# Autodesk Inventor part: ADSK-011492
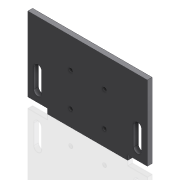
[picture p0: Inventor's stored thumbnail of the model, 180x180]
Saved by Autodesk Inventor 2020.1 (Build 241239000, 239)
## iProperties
Created: 2000-02
Part Number: ADSK-011492
Material: RA HRS
Description: PLT-24,FH,CP,02,060,040,NNCCCC,PLATE,MNT
Document SubType Name: Modeling
Designer: sspink
Density: 7.83 g/cm^3
Appearance: Métal - Acier
Mass: 672.294 g
Surface Area: 330.042 cm^2
Volume: 85.8613 cm^3
Control State: 0
Checked Out: False
Master: False
Shininess: 0.0
Length Units: 11269
Angle Units: 11279
Time Units: 11290
Mass Units: 11283
Length Display Precision: 3
Angle Display Precision: 2
Compacted: True
Cutlength: 6
Material Desc: FLAT,HRS,0.25 X 4.00
Material_number: A084338
Dimensions: 152x101x6 mm
Mass: 0,672 kg
DocNumber: ADSK-011492.ipt
Folder: 01 - Themengebiete\Simplification\01 - Packaging machine\
VDS_Category: 3D Komponenten
Density: 0.0
Volumn: 0.0
Area: 0.0
PropertySet Name: Model Information
Author: sspink
Revision Number: -
Title: PLT-24,FH,CP,02,060,040,NNCCCC,PLATE,MNT
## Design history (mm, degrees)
node "Solide1"
  node "Extrusion1" dims "d2" = 6, "d3" = 0
  node "Extrusion2" dims "d13" = 25.4, "d14" = 0
  node "Extrusion3" dims "d19" = 25.4, "d20" = 0
  node "Hole1" dims "d25" = 4.917, "d26" = 9.525, "d27" = 6.35, "d28" = 60 deg, "d29" = 17.1, "d30" = 118 deg, "d35" = 12
sketch "Sketch1"
  geometry: L1 (0, 0)-(152, 0); L2 (152, 0)-(152, 101); L3 (152, 101)-(0, 101); L4 (0, 101)-(0, 0)
  constraints: 8 end point, 2 parallel, 1 horizontal, 1 perpendicular
  dimensions: "d0" = 101 distance between parallel lines of L1 L3; "d1" = 152 distance between parallel lines of L2 L4
sketch "Sketch2"
  geometry: L1 (0, 101)-(0, 0) reference; L2 (-152, 0)-(-152, 101) reference; L3 (-7.5, 18.5)-(-17.5, 18.5); L4 (-17.5, 18.5)-(-17.5, 43.5); L5 (-17.5, 43.5)-(-7.5, 43.5); L6 (-7.5, 43.5)-(-7.5, 18.5); L7 (-134.5, 18.5)-(-144.5, 18.5); L8 (-144.5, 18.5)-(-144.5, 43.5); L9 (-144.5, 43.5)-(-134.5, 43.5); L10 (-134.5, 43.5)-(-134.5, 18.5); L11 (0, 50.5)-(-152, 50.5); L12 (-139.5, 43.5)-(-139.5, 18.5); L13 (-12.5, 43.5)-(-12.5, 18.5); L14 (-139.5, 31)-(-12.5, 31); A1 r 5 centre (-12.5, 18.5) between (-17.5, 18.5) and (-7.5, 18.5); A2 r 5 centre (-12.5, 43.5) between (-7.5, 43.5) and (-17.5, 43.5); A3 r 5 centre (-139.5, 43.5) between (-134.5, 43.5) and (-144.5, 43.5); A4 r 5 centre (-139.5, 18.5) between (-144.5, 18.5) and (-134.5, 18.5); 2 further points
  constraints: 24 end point, 8 point on circle, 6 midpoint, 4 centre point, 4 parallel, 4 tangent, 2 collinear, 2 horizontal, 2 perpendicular, 2 vertical, 1 vertical alignment
  dimensions: "d4" = 25 distance of L3.end L4.end (= d5); "d5" = 25 distance of L9.end L7.start; "d6" = 10 distance of L3.start L3.end; "d12" = 32 distance from line of L12.end L11; "d31" = 127 distance of L14.start L14.end
workplane "Arbeitsebene1"
workplane "Arbeitsebene2"
sketch "Sketch3"
  geometry: L1 (0, 0)-(-152, 0) reference; L2 (0, 101)-(0, 0) reference; L3 (-152, 0)-(-152, 101) reference; L4 (0, 6.35)-(-25, 6.35); L5 (-25, 6.35)-(-25, 0); L6 (-152, 6)-(-127, 6); L7 (-127, 6)-(-127, 0)
  constraints: 8 end point, 4 perpendicular, 4 point on line
  dimensions: "d15" = 25 distance of L4.start L4.end; "d16" = 25 distance of L6.start L6.end (= d15); "d17" = 6 distance between parallel lines of L6 L1; "d18" = 6.35 distance between parallel lines of L1 L4
sketch "Sketch4"
  geometry: L1 (0, 101)-(152, 101) reference; L2 (127, 0)-(25, 0) reference; L3 (76, 101)-(76, 0); L4 (54.5, 63)-(97.5, 63); L5 (97.5, 63)-(97.5, 20); L6 (97.5, 20)-(54.5, 20); L7 (54.5, 20)-(54.5, 63); 3 further points
  constraints: 10 end point, 3 midpoint, 2 parallel, 1 horizontal, 1 perpendicular, 1 point on line
  dimensions: "d32" = 43 distance of L4.start L4.end; "d33" = 43 distance of L6.end L4.start (= d32); "d34" = 20 distance between parallel lines of L2 L6
node "Corps solides"
node "Corps surfaciques"
